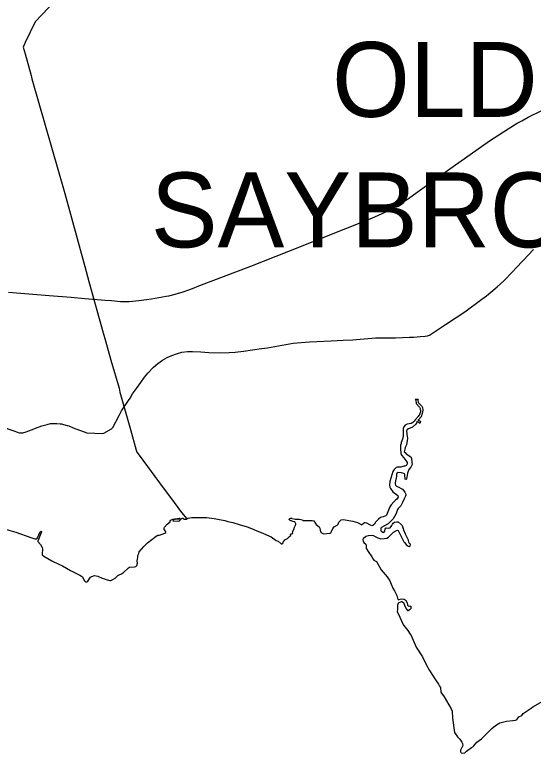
# Model space of a CAD drawing. Extents: x 0 to 2603, y -226 to 830.
# Drawn here: x 247.85 to 257.21, y 521.04 to 534.36 of the extents above; entities that cross this region are included whole.
import ezdxf

# ---------------------------------------------------------------- set-up
doc = ezdxf.new("R2010")
doc.units = 0
for name, color, linetype in [('CT_TSH_Map_Interstate_Roads', 7, 'Continuous'), ('CT_TSH_Map_Town_Limits', 7, 'Continuous'), ('CT_TSH_Map_Town_Text', 7, 'Continuous'), ('CT_TSH_Map_US_and_State_Routes', 7, 'Continuous')]:
    doc.layers.add(name, color=color, linetype=linetype)

msp = doc.modelspace()

# ---------------------------------------------------------------- linework, layer by layer
at = {"layer": 'CT_TSH_Map_Interstate_Roads'}
for points in [[(257.002, 532.447), (257.12, 532.514), (257.365, 532.633)], [(256.756, 532.299), (256.92, 532.401)], [(256.92, 532.401), (257.002, 532.447)], [(255.664, 531.548), (256.422, 532.084), (256.756, 532.299)], [(255.117, 531.159), (255.551, 531.47)], [(255.551, 531.47), (255.664, 531.548)], [(254.793, 530.934), (254.957, 531.044)], [(254.957, 531.044), (255.117, 531.159)], [(254.296, 530.692), (254.536, 530.799), (254.638, 530.844), (254.732, 530.894), (254.793, 530.934)], [(252.797, 530.096), (253.826, 530.502), (254.296, 530.692)], [(251.177, 529.469), (252.111, 529.826), (252.797, 530.096)], [(250.634, 529.292), (250.748, 529.317), (250.893, 529.364), (251.062, 529.424), (251.177, 529.469)], [(247.743, 529.354), (248.472, 529.296), (248.872, 529.263)], [(248.872, 529.263), (249.118, 529.243)], [(249.118, 529.243), (249.488, 529.211)], [(249.488, 529.211), (249.598, 529.204)], [(249.598, 529.204), (249.762, 529.19), (249.918, 529.19)], [(249.918, 529.19), (250.095, 529.208)], [(250.095, 529.208), (250.231, 529.221), (250.32, 529.237)], [(250.32, 529.237), (250.588, 529.282), (250.634, 529.292)]]:
    msp.add_lwpolyline(points, dxfattribs=at)
at = {"layer": 'CT_TSH_Map_Town_Limits'}
for points in [[(248.582, 534.612), (248.22, 534.229), (248.041, 533.859), (248.008, 533.774), (248.04, 533.652), (248.148, 533.265), (248.163, 533.202), (248.755, 531.132), (249.117, 529.82), (249.191, 529.549), (249.447, 528.624), (249.491, 528.476), (249.589, 528.13), (249.737, 527.625), (249.749, 527.555), (249.943, 526.878), (250.044, 526.507), (250.059, 526.471), (250.096, 526.417), (250.531, 525.826), (250.683, 525.627), (250.845, 525.408), (250.892, 525.344), (250.958, 525.269)], [(255.13, 527.421), (255.079, 527.418)], [(255.079, 527.418), (255.089, 527.407), (255.097, 527.346)], [(255.097, 527.346), (255.155, 527.285), (255.167, 527.261), (255.167, 527.249)], [(255.13, 527.421), (255.124, 527.405), (255.135, 527.369), (255.196, 527.302), (255.213, 527.275), (255.217, 527.229), (255.204, 527.166), (255.184, 527.105), (255.141, 527.053)], [(255.167, 527.249), (255.175, 527.229), (255.176, 527.199), (255.161, 527.164)], [(255.079, 527.055), (255.061, 527.029), (255.034, 527.007)], [(255.13, 527.111), (255.079, 527.055)], [(255.141, 527.053), (255.129, 527.046), (255.173, 527.027), (255.17, 527.006), (255.16, 526.989), (255.137, 527.01), (255.111, 527.023), (255.108, 527.003)], [(255.161, 527.164), (255.147, 527.131), (255.13, 527.111)], [(254.922, 526.97), (254.898, 526.955), (254.873, 526.928), (254.862, 526.899), (254.861, 526.819), (254.863, 526.764), (254.852, 526.705), (254.828, 526.644), (254.827, 526.629)], [(255.034, 527.007), (255.007, 526.987), (254.932, 526.976), (254.922, 526.97)], [(255.108, 527.003), (255.088, 526.976), (255.029, 526.923), (254.961, 526.891), (254.926, 526.872), (254.924, 526.843)], [(254.924, 526.843), (254.928, 526.813), (254.93, 526.794)], [(254.93, 526.794), (254.936, 526.762), (254.94, 526.722)], [(254.933, 526.674), (254.93, 526.645), (254.921, 526.602)], [(254.94, 526.722), (254.933, 526.674)], [(254.813, 526.55), (254.812, 526.519)], [(254.812, 526.519), (254.819, 526.464)], [(254.827, 526.629), (254.816, 526.597), (254.813, 526.55)], [(254.894, 526.527), (254.879, 526.475), (254.899, 526.462)], [(254.921, 526.602), (254.899, 526.557), (254.894, 526.527)], [(254.819, 526.464), (254.821, 526.447), (254.834, 526.419), (254.874, 526.369)], [(254.899, 526.462), (254.915, 526.442), (254.999, 526.389)], [(254.999, 526.389), (255.012, 526.358), (255.016, 526.29), (255.024, 526.249), (255.002, 526.203), (254.964, 526.158), (254.938, 526.092), (254.934, 526.053)], [(254.934, 526.261), (254.931, 526.244), (254.914, 526.228), (254.89, 526.217), (254.873, 526.217)], [(254.874, 526.369), (254.913, 526.323), (254.933, 526.286), (254.934, 526.261)], [(254.678, 526.122), (254.621, 525.939), (254.614, 525.874), (254.621, 525.84), (254.631, 525.813), (254.675, 525.754), (254.768, 525.688), (254.772, 525.668)], [(254.753, 526.199), (254.733, 526.193), (254.697, 526.16), (254.678, 526.122)], [(254.873, 526.217), (254.817, 526.198), (254.792, 526.203), (254.753, 526.199)], [(254.732, 525.984), (254.716, 525.918)], [(254.741, 526.045), (254.738, 525.998), (254.732, 525.984)], [(254.892, 526.047), (254.892, 526.065), (254.888, 526.078), (254.877, 526.087), (254.829, 526.097), (254.774, 526.101), (254.751, 526.094), (254.74, 526.087), (254.741, 526.045)], [(254.896, 525.993), (254.892, 526.047)], [(254.922, 525.986), (254.918, 525.98), (254.901, 525.986), (254.896, 525.993)], [(254.934, 526.053), (254.929, 526.018), (254.922, 525.986)], [(254.716, 525.918), (254.716, 525.901), (254.725, 525.878), (254.739, 525.86), (254.786, 525.842), (254.827, 525.818)], [(254.827, 525.818), (254.849, 525.802), (254.893, 525.747), (254.906, 525.725)], [(254.906, 525.725), (254.911, 525.696), (254.907, 525.677), (254.883, 525.63), (254.851, 525.564)], [(254.721, 525.604), (254.691, 525.578), (254.645, 525.522), (254.624, 525.484), (254.56, 525.335), (254.549, 525.32), (254.529, 525.317)], [(254.772, 525.668), (254.772, 525.657), (254.743, 525.615), (254.721, 525.604)], [(254.773, 525.455), (254.76, 525.438), (254.746, 525.4), (254.735, 525.367)], [(254.851, 525.564), (254.817, 525.501), (254.777, 525.462), (254.773, 525.455)], [(254.529, 525.317), (254.503, 525.307), (254.453, 525.295), (254.414, 525.265), (254.357, 525.202)], [(254.735, 525.367), (254.707, 525.308), (254.681, 525.269)], [(246.456, 525.228), (246.517, 525.209), (246.628, 525.208), (246.716, 525.235), (246.789, 525.246), (246.842, 525.258), (246.9, 525.254), (246.924, 525.249), (247.009, 525.211), (247.157, 525.199), (247.301, 525.174), (247.448, 525.134), (247.627, 525.101), (247.749, 525.063), (247.875, 525.03), (248.147, 524.931), (248.219, 524.906), (248.237, 524.905), (248.254, 524.909), (248.267, 524.923), (248.311, 525.035), (248.332, 525.044), (248.336, 525.04)], [(248.325, 525.003), (248.282, 524.894), (248.269, 524.866), (248.269, 524.857), (248.321, 524.807), (248.349, 524.75), (248.355, 524.727), (248.346, 524.631), (248.35, 524.62), (248.381, 524.593), (248.521, 524.512), (248.662, 524.445), (248.715, 524.423), (248.859, 524.335), (249.031, 524.252), (249.075, 524.22), (249.098, 524.167), (249.111, 524.148), (249.133, 524.133), (249.154, 524.134), (249.17, 524.147), (249.223, 524.214), (249.243, 524.231), (249.292, 524.248), (249.35, 524.236), (249.429, 524.201), (249.474, 524.188), (249.505, 524.174), (249.571, 524.157), (249.589, 524.159), (249.626, 524.172), (249.663, 524.196), (249.714, 524.245), (249.739, 524.26), (249.777, 524.275), (249.816, 524.299), (249.908, 524.386), (249.922, 524.394), (250.015, 524.401), (250.037, 524.406), (250.057, 524.426), (250.066, 524.467), (250.065, 524.511), (250.075, 524.574), (250.072, 524.606), (250.094, 524.646), (250.1, 524.673), (250.182, 524.767), (250.249, 524.833), (250.407, 524.956), (250.433, 524.971), (250.464, 524.976), (250.559, 525.012), (250.577, 525.024), (250.578, 525.034), (250.571, 525.049), (250.548, 525.078), (250.547, 525.106), (250.554, 525.121), (250.602, 525.173), (250.658, 525.213), (250.661, 525.237), (250.674, 525.252), (250.707, 525.265), (250.82, 525.282), (250.829, 525.279), (250.832, 525.274), (250.815, 525.26), (250.747, 525.255), (250.711, 525.248), (250.707, 525.235), (250.716, 525.23), (250.8, 525.226), (250.826, 525.234), (250.859, 525.267), (250.873, 525.28), (250.887, 525.278), (250.908, 525.258)], [(250.913, 525.263), (250.952, 525.265), (250.958, 525.269)], [(250.958, 525.269), (250.979, 525.283), (251.047, 525.294), (251.203, 525.295), (251.315, 525.292), (251.452, 525.275), (251.644, 525.239), (251.701, 525.222), (251.787, 525.205), (251.901, 525.166), (252.046, 525.126), (252.097, 525.109)], [(252.662, 524.82), (252.676, 524.82), (252.694, 524.833), (252.699, 524.851), (252.712, 524.873), (252.727, 524.887), (252.773, 524.911), (252.784, 524.921), (252.787, 524.931), (252.816, 524.957), (252.836, 524.968), (252.831, 524.991), (252.839, 524.999), (252.859, 525), (252.869, 525.009), (252.867, 525.033), (252.897, 525.09), (252.9, 525.121), (252.924, 525.167), (252.927, 525.18), (252.91, 525.212), (252.871, 525.22), (252.844, 525.232), (252.844, 525.238)], [(252.806, 525.251), (252.815, 525.281)], [(252.806, 525.251), (252.844, 525.238)], [(252.859, 525.273), (252.826, 525.276), (252.815, 525.281)], [(252.859, 525.273), (252.916, 525.265), (252.984, 525.264), (253.044, 525.249), (253.054, 525.24)], [(253.054, 525.24), (253.132, 525.238), (253.219, 525.241), (253.253, 525.23), (253.279, 525.183), (253.294, 525.167), (253.347, 525.126), (253.358, 525.099), (253.365, 525.065), (253.379, 525.029), (253.388, 525.016), (253.424, 525.001), (253.546, 525.013), (253.558, 525.016), (253.563, 525.027)], [(253.563, 525.027), (253.593, 525.094), (253.618, 525.126), (253.673, 525.153), (253.688, 525.17), (253.7, 525.208), (253.732, 525.241), (253.745, 525.249), (253.781, 525.258), (253.956, 525.229), (254.036, 525.205), (254.116, 525.161)], [(254.312, 525.149), (254.296, 525.145), (254.258, 525.159), (254.205, 525.19), (254.179, 525.196), (254.162, 525.195), (254.119, 525.16), (254.116, 525.161)], [(254.357, 525.202), (254.353, 525.179), (254.318, 525.152), (254.312, 525.149)], [(254.681, 525.269), (254.591, 525.181), (254.513, 525.134), (254.469, 525.112), (254.458, 525.102)], [(254.518, 525.03), (254.527, 525.039), (254.545, 525.102), (254.558, 525.108), (254.602, 525.101), (254.625, 525.104), (254.657, 525.151), (254.668, 525.175), (254.683, 525.192), (254.703, 525.207), (254.748, 525.216), (254.77, 525.214)], [(254.77, 525.214), (254.825, 525.169)], [(252.097, 525.109), (252.28, 525.029), (252.302, 525.022)], [(254.458, 525.102), (254.459, 525.057), (254.467, 525.048)], [(254.467, 525.048), (254.493, 525.028), (254.503, 525.025), (254.516, 525.028), (254.518, 525.03)], [(254.566, 524.92), (254.597, 524.938), (254.69, 525.026), (254.742, 525.058), (254.76, 525.062), (254.772, 525.056), (254.798, 525.012), (254.841, 524.913)], [(254.825, 525.169), (254.842, 525.147), (254.858, 525.115)], [(254.987, 524.815), (254.977, 524.822), (254.964, 524.847), (254.956, 524.883), (254.902, 524.992), (254.873, 525.065), (254.866, 525.097), (254.858, 525.115)], [(248.336, 525.04), (248.331, 525.008)], [(252.302, 525.022), (252.478, 524.943), (252.57, 524.88), (252.607, 524.864), (252.662, 524.82)], [(254.332, 524.961), (254.31, 524.969), (254.23, 524.964), (254.19, 524.951), (254.143, 524.91)], [(254.332, 524.961), (254.403, 524.924), (254.458, 524.909)], [(254.458, 524.909), (254.517, 524.913)], [(254.517, 524.913), (254.566, 524.92)], [(254.841, 524.913), (254.877, 524.851), (254.886, 524.841)], [(254.138, 524.905), (254.134, 524.896), (254.143, 524.857), (254.152, 524.841), (254.189, 524.812), (254.193, 524.8), (254.195, 524.747), (254.199, 524.729), (254.229, 524.677), (254.297, 524.586), (254.32, 524.543), (254.335, 524.526), (254.379, 524.5), (254.468, 524.35), (254.573, 524.223), (254.598, 524.188), (254.619, 524.149)], [(254.886, 524.841), (254.931, 524.79), (254.954, 524.774), (254.982, 524.767)], [(254.987, 524.815), (254.982, 524.767)], [(254.619, 524.149), (254.643, 524.088), (254.674, 524.02), (254.707, 523.97), (254.729, 523.921), (254.744, 523.898), (254.746, 523.888)], [(254.746, 523.888), (254.758, 523.839), (254.773, 523.812), (254.781, 523.809)], [(254.778, 523.751), (254.771, 523.747), (254.762, 523.714)], [(254.778, 523.751), (254.832, 523.777), (254.839, 523.779), (254.87, 523.757), (254.9, 523.68), (254.922, 523.637)], [(254.999, 523.695), (254.968, 523.69), (254.958, 523.694), (254.948, 523.706), (254.948, 523.724), (254.941, 523.747), (254.917, 523.79), (254.879, 523.812), (254.824, 523.817), (254.781, 523.809)], [(254.762, 523.714), (254.759, 523.634), (254.752, 523.598), (254.803, 523.496), (254.848, 523.39), (254.874, 523.345), (254.945, 523.256), (254.987, 523.188), (255.006, 523.164), (255.096, 522.953), (255.212, 522.778), (255.271, 522.655), (255.339, 522.533), (255.448, 522.365), (255.502, 522.289), (255.518, 522.25), (255.534, 522.226), (255.544, 522.144), (255.552, 522.123), (255.601, 522.059), (255.727, 521.844), (255.747, 521.801), (255.752, 521.672), (255.79, 521.417), (255.843, 521.34), (255.887, 521.294), (255.923, 521.243), (255.934, 521.218), (255.938, 521.182), (255.895, 521.097), (255.897, 521.065), (255.901, 521.061)], [(254.922, 523.637), (254.943, 523.613), (254.954, 523.617), (254.978, 523.636)], [(254.978, 523.636), (254.999, 523.648)], [(254.999, 523.695), (254.999, 523.648)], [(256.921, 521.658), (256.946, 521.696), (257.001, 521.725), (257.03, 521.756), (257.172, 521.852), (257.199, 521.877), (257.38, 521.983), (257.468, 522.01), (257.492, 522.008)], [(256.498, 521.516), (256.544, 521.556), (256.607, 521.591), (256.725, 521.621), (256.842, 521.633)], [(256.842, 521.633), (256.889, 521.637), (256.905, 521.644), (256.921, 521.658)], [(255.901, 521.061), (255.911, 521.051), (255.932, 521.042), (255.975, 521.049), (256.002, 521.081), (256.095, 521.146), (256.119, 521.158), (256.14, 521.178), (256.19, 521.24), (256.274, 521.303), (256.46, 521.487), (256.498, 521.516)]]:
    msp.add_lwpolyline(points, dxfattribs=at)
at = {"layer": 'CT_TSH_Map_US_and_State_Routes'}
for points in [[(257.025, 529.924), (257.214, 530.128)], [(256.896, 529.786), (257.025, 529.924)], [(256.676, 529.563), (256.843, 529.731)], [(256.843, 529.731), (256.896, 529.786)], [(256.365, 529.29), (256.556, 529.45), (256.676, 529.563)], [(255.336, 528.582), (255.626, 528.773), (255.972, 529.004), (256.282, 529.229)], [(256.282, 529.229), (256.365, 529.29)], [(254.086, 528.506), (254.157, 528.512)], [(254.157, 528.512), (254.364, 528.532), (254.531, 528.535)], [(254.531, 528.535), (254.723, 528.535), (254.976, 528.544)], [(254.976, 528.544), (255.049, 528.547)], [(255.049, 528.547), (255.116, 528.553)], [(255.116, 528.553), (255.167, 528.554)], [(255.167, 528.554), (255.26, 528.562), (255.304, 528.569), (255.336, 528.582)], [(252.412, 528.354), (252.745, 528.412), (252.876, 528.435), (253.171, 528.46)], [(253.171, 528.46), (253.561, 528.48)], [(253.561, 528.48), (253.78, 528.489)], [(253.78, 528.489), (253.954, 528.497)], [(253.954, 528.497), (254.086, 528.506)], [(250.522, 528.131), (250.603, 528.178), (250.689, 528.213), (250.789, 528.251)], [(250.789, 528.251), (250.87, 528.274)], [(250.87, 528.274), (250.969, 528.285), (251.058, 528.288), (251.21, 528.281), (251.358, 528.27)], [(251.358, 528.27), (251.572, 528.261)], [(251.572, 528.261), (251.72, 528.269), (251.828, 528.275), (251.984, 528.294)], [(251.984, 528.294), (252.304, 528.34)], [(252.304, 528.34), (252.412, 528.354)], [(250.255, 527.894), (250.356, 528.004), (250.437, 528.071), (250.522, 528.131)], [(250.196, 527.825), (250.255, 527.894)], [(250.05, 527.621), (250.126, 527.724)], [(250.126, 527.724), (250.196, 527.825)], [(249.74, 527.13), (249.78, 527.215), (249.909, 527.404), (249.938, 527.447), (249.98, 527.52), (250.05, 527.621)], [(249.441, 526.806), (249.463, 526.812), (249.599, 526.89), (249.622, 526.913), (249.74, 527.13)], [(247.54, 526.971), (247.731, 526.892), (247.84, 526.853), (247.906, 526.83), (247.932, 526.822), (247.965, 526.822)], [(248.175, 526.882), (248.229, 526.901), (248.343, 526.943), (248.436, 526.972), (248.498, 526.985), (248.611, 526.99), (248.675, 526.982)], [(248.675, 526.982), (248.699, 526.98), (248.735, 526.972)], [(248.735, 526.972), (248.797, 526.954), (248.832, 526.943), (248.905, 526.909)], [(247.965, 526.822), (248, 526.822), (248.061, 526.839), (248.091, 526.852)], [(248.091, 526.852), (248.175, 526.882)], [(248.905, 526.909), (249.157, 526.819)], [(249.157, 526.819), (249.441, 526.806)]]:
    msp.add_lwpolyline(points, dxfattribs=at)

# ---------------------------------------------------------------- texts
at = {"layer": 'CT_TSH_Map_Town_Text'}
for s, p in [('OLD', (253.579, 532.517)), ('SAYBROOK', (250.309, 530.164))]:
    msp.add_text(s, height=1.35, dxfattribs=at).set_placement(p)

doc.saveas('drawing.dxf')
